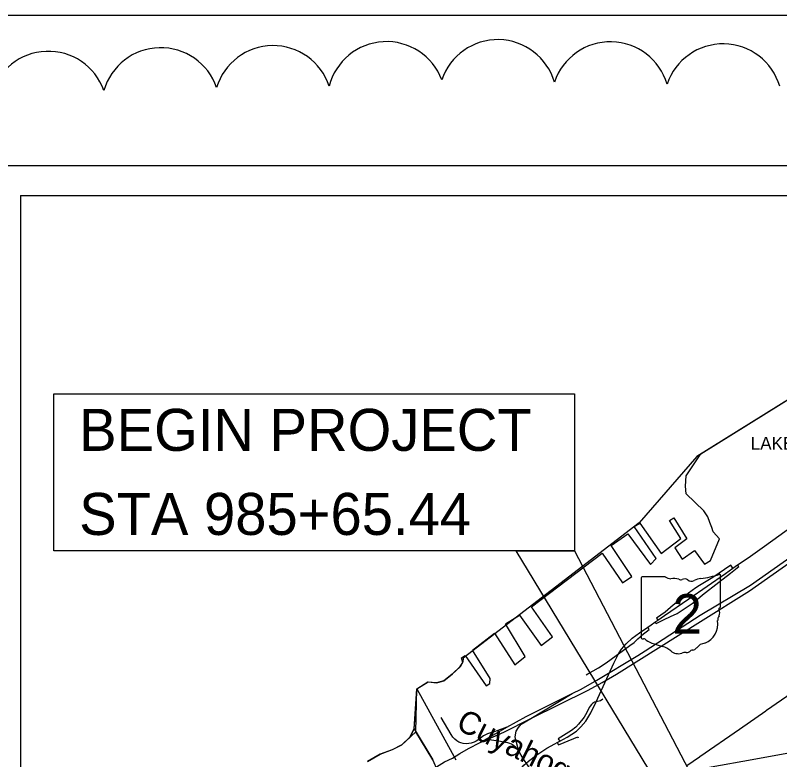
# Model space of a CAD drawing. Extents: x 0 to 96.2, y -27.5 to 31.3.
# Drawn here: x 43.806 to 46.354, y 18.907 to 21.387 of the extents above; entities that cross this region are included whole.
import ezdxf

# ---------------------------------------------------------------- set-up
doc = ezdxf.new("R2010")
doc.units = 0
for name, color, linetype in [('BOTTOM-BLKS', 7, 'Continuous'), ('DIM', 7, 'Continuous'), ('TB1', 7, 'Continuous'), ('TB_DUAL_PROF', 7, 'Continuous'), ('TB_INDEX', 7, 'Continuous'), ('TB_PIPEMAT', 7, 'Continuous'), ('TB_PP_20x10', 7, 'Continuous'), ('TB_PP_30x10_GRID', 7, 'Continuous'), ('TB_PP_50x10_GRID', 7, 'Continuous'), ('TB_PROF_20x5_GRID', 7, 'Continuous'), ('TB_PSDSOD', 7, 'Continuous'), ('TB_SIGN_XS', 7, 'Continuous'), ('TB_SUPER_50x1', 7, 'Continuous'), ('TB_SUPER_50x1_GRID', 7, 'Continuous')]:
    doc.layers.add(name, color=color, linetype=linetype)

msp = doc.modelspace()

# ---------------------------------------------------------------- linework, layer by layer
at = {"layer": 'BOTTOM-BLKS'}
msp.add_lwpolyline([(47.5697, 20.7869), (47.5549, 20.7755), (47.5401, 20.7686), (47.3142, 20.6769), (47.2957, 20.6616), (47.2821, 20.6527), (47.2613, 20.6537), (46.0779, 19.9176), (45.8857, 19.6966), (45.2991, 19.2457), (45.2981, 19.2331), (45.2884, 19.2171), (45.2624, 19.1925), (45.2337, 19.1699), (45.2098, 19.1632), (45.181, 19.166), (45.1439, 19.1425), (45.1344, 19.0097), (45.1214, 18.9823), (45.0939, 18.9569), (45.0625, 18.9403), (45.0216, 18.9255), (44.9794, 18.9013)], dxfattribs=at)
at = {"layer": 'DIM'}
msp.add_lwpolyline([(43.2234, 21.3869), (74.7234, 21.3869), (74.7234, 0.3869), (43.2234, 0.3869)], close=True, dxfattribs=at)
at = {"layer": 'TB1'}
for p, q in [((43.7234, 20.8869), (50.7234, 20.8869)), ((43.8234, 20.7869), (43.8234, 13.9869)), ((43.8234, 20.7869), (50.6234, 20.7869))]:
    msp.add_line(p, q, dxfattribs=at)
at = {"layer": 'TB_DUAL_PROF'}
for p, q in [((45.9722, 19.5167), (45.895, 19.5167)), ((46.156, 19.4169), (46.156, 19.5216)), ((45.8924, 19.5132), (45.8924, 19.3131)), ((46.156, 19.417), (46.156, 19.4169))]:
    msp.add_line(p, q, dxfattribs=at)
for centre, radius, start, end in [((45.8954, 19.5136), 0.00305, 98.1301, 188.1301), ((45.9906, 19.5399), 0.0296, 231.6195, 271.1119), ((46.0621, 19.7895), 0.2796, 275.8445, 288.9065), ((46.1531, 19.5221), 0.00294, 351.8621, 97.738), ((46.0004, 19.4043), 0.1064, 80.4867, 94.9883), ((46.0245, 19.5147), 0.00855, 219.7921, 297.1024), ((46.0371, 19.4916), 0.0178, 54.4667, 119.1411), ((46.06, 19.5233), 0.0214, 233.8562, 294.8282), ((46.0978, 19.4555), 0.0563, 97.3462, 120.7689), ((46.1554, 19.4093), 0.00454, 107.944, 210.337), ((46.1529, 19.4165), 0.00314, 289.6038, 7.7341), ((46.1265, 19.396), 0.0273, 340.033, 23.6496), ((46.0778, 19.3598), 0.0699, 292.3089, 8.9858), ((46.1666, 19.3731), 0.0198, 136.8065, 186.9296), ((45.8954, 19.3127), 0.00308, 171.9584, 258.3066), ((45.8959, 19.3331), 0.0235, 267.339, 280.6039), ((45.9007, 19.3016), 0.00848, 29.7484, 93.2717), ((46.0078, 19.4814), 0.2019, 240.4129, 257.1985), ((46.1073, 19.2569), 0.0383, 94.4031, 142.5768), ((45.9476, 19.2232), 0.0632, 47.1842, 75.836), ((46.0159, 19.3006), 0.0401, 230.7004, 286.2918), ((46.0391, 19.2314), 0.0329, 85.6951, 111.2099), ((46.042, 19.2856), 0.0214, 268.777, 315.5493), ((46.0613, 19.2662), 0.00601, 65.7517, 132.6484), ((46.0587, 19.2937), 0.0226, 282.8732, 323.2771)]:
    msp.add_arc(centre, radius, start, end, dxfattribs=at)
at = {"layer": 'TB_INDEX'}
for points in [[(45.2973, 19.2309), (45.2927, 19.2462), (45.3055, 19.2547), (45.3755, 19.1539), (45.3871, 19.1609), (45.3884, 19.1777), (45.3303, 19.2726), (45.4027, 19.3285), (45.4709, 19.2234), (45.505, 19.2506), (45.4402, 19.3599), (45.4861, 19.3883), (45.5591, 19.2879), (45.5963, 19.317), (45.5259, 19.4163), (45.7621, 19.5956), (45.8302, 19.4962), (45.8302, 19.4962), (45.861, 19.5172), (45.7921, 19.6211), (45.847, 19.6592), (45.9227, 19.5581), (45.9414, 19.577), (45.8682, 19.6843), (45.887, 19.6956), (45.9589, 19.5944), (46.0239, 19.6441), (45.9865, 19.704), (46.0011, 19.7129), (46.044, 19.6432), (46.0039, 19.6133), (46.0284, 19.5753), (46.0701, 19.6037), (46.1035, 19.5589), (46.1227, 19.5706), (46.1535, 19.643), (46.1314, 19.6662), (46.1278, 19.681), (46.1203, 19.6972), (46.1143, 19.7165), (46.1003, 19.7361), (46.042, 19.793), (46.0397, 19.8181), (46.0419, 19.8527), (46.0911, 19.9258)], [(45.1413, 19.0003), (45.1448, 19.143)], [(45.1448, 19.143), (45.2744, 18.9074)], [(45.1448, 19.143), (45.2744, 18.9074)], [(45.1353, 19.0102), (45.1974, 18.9074)], [(45.1974, 18.9074), (45.1413, 19.0003)], [(45.2137, 18.869), (45.1974, 18.9074)]]:
    msp.add_lwpolyline(points, dxfattribs=at)
at = {"layer": 'TB_PIPEMAT'}
msp.add_line((45.1413, 19.0003), (45.1448, 19.143), dxfattribs=at)
for points in [[(46.0911, 19.9258), (47.2621, 20.6542), (47.283, 20.6532), (47.288, 20.6565)], [(45.2973, 19.2309), (45.2927, 19.2462), (45.3055, 19.2547), (45.3755, 19.1539), (45.3871, 19.1609), (45.3884, 19.1777), (45.3303, 19.2726), (45.4027, 19.3285), (45.4709, 19.2234), (45.505, 19.2506), (45.4402, 19.3599), (45.4861, 19.3883), (45.5591, 19.2879), (45.5963, 19.317), (45.5259, 19.4163), (45.7621, 19.5956), (45.8302, 19.4962), (45.8302, 19.4962), (45.861, 19.5172), (45.7921, 19.6211), (45.847, 19.6592), (45.9227, 19.5581), (45.9414, 19.577), (45.8682, 19.6843), (45.887, 19.6956), (45.9589, 19.5944), (46.0239, 19.6441), (45.9865, 19.704), (46.0011, 19.7129), (46.044, 19.6432), (46.0039, 19.6133), (46.0284, 19.5753), (46.0701, 19.6037), (46.1035, 19.5589), (46.1227, 19.5706), (46.1535, 19.643), (46.1314, 19.6662), (46.1278, 19.681), (46.1203, 19.6972), (46.1143, 19.7165), (46.1003, 19.7361), (46.042, 19.793), (46.0397, 19.8181), (46.0419, 19.8527), (46.0911, 19.9258)], [(45.2973, 19.2309), (45.2927, 19.2462), (45.3055, 19.2547), (45.3755, 19.1539), (45.3871, 19.1609), (45.3884, 19.1777), (45.3303, 19.2726), (45.4027, 19.3285), (45.4709, 19.2234), (45.505, 19.2506), (45.4402, 19.3599), (45.4861, 19.3883), (45.5591, 19.2879), (45.5963, 19.317), (45.5259, 19.4163), (45.7621, 19.5956), (45.8302, 19.4962), (45.8302, 19.4962), (45.861, 19.5172), (45.7921, 19.6211), (45.847, 19.6592), (45.9227, 19.5581), (45.9414, 19.577), (45.8682, 19.6843), (45.887, 19.6956), (45.9589, 19.5944), (46.0239, 19.6441), (45.9865, 19.704), (46.0011, 19.7129), (46.044, 19.6432), (46.0039, 19.6133), (46.0284, 19.5753), (46.0701, 19.6037), (46.1035, 19.5589), (46.1227, 19.5706), (46.1535, 19.643), (46.1314, 19.6662), (46.1278, 19.681), (46.1203, 19.6972), (46.1143, 19.7165), (46.1003, 19.7361), (46.042, 19.793), (46.0397, 19.8181), (46.0419, 19.8527), (46.0911, 19.9258)], [(44.9802, 18.9018), (45.0224, 18.926), (45.0633, 18.9408), (45.0947, 18.9574), (45.1222, 18.9827), (45.1353, 19.0102), (45.1448, 19.143), (45.1818, 19.1665), (45.2107, 19.1637), (45.2345, 19.1703), (45.2632, 19.193), (45.2892, 19.2176), (45.2973, 19.2309)], [(45.1448, 19.143), (45.1818, 19.1665), (45.2107, 19.1637), (45.2345, 19.1703), (45.2632, 19.193), (45.2892, 19.2176), (45.2973, 19.2309)], [(44.9802, 18.9018), (45.0224, 18.926), (45.0633, 18.9408), (45.0947, 18.9574), (45.1413, 19.0003)]]:
    msp.add_lwpolyline(points, dxfattribs=at)
at = {"layer": 'TB_PP_50x10_GRID'}
for points in [[(45.9055, 19.2703), (46.0888, 19.3884), (46.2568, 19.4882), (46.6429, 19.7608), (46.9371, 19.9661), (47.0729, 20.0637), (47.1791, 20.1395), (47.2478, 20.1879), (47.3438, 20.2535), (47.478, 20.3432), (47.913, 20.6171), (48.0033, 20.6774)], [(45.5238, 19.0447), (45.7156, 19.1389), (45.7618, 19.165), (45.8095, 19.1926), (46.0898, 19.368), (46.2526, 19.4701), (46.4704, 19.6234), (46.5126, 19.6515), (46.5391, 19.6663), (46.5763, 19.6846), (46.6015, 19.6954), (46.6221, 19.7035), (46.6462, 19.7132), (46.9167, 19.8209), (46.9722, 19.8425)], [(45.6618, 19.1283), (45.6915, 19.1425), (45.7438, 19.1721), (45.8804, 19.2541), (45.9055, 19.2703)], [(45.4443, 19.0158), (45.5081, 19.0509), (45.6618, 19.1283)], [(45.5238, 19.0447), (45.6618, 19.1283)], [(45.4443, 19.0158), (45.4144, 19.0044), (45.4024, 19.0005), (45.39, 18.9969), (45.3797, 18.9933), (45.3734, 18.9907), (45.3669, 18.9871), (45.3568, 18.9789), (45.3478, 18.9723), (45.342, 18.9687), (45.335, 18.9654), (45.3255, 18.9626), (45.3176, 18.9611), (45.3084, 18.9604), (45.2989, 18.9611), (45.2912, 18.9634), (45.284, 18.9662), (45.2777, 18.97), (45.2705, 18.9755), (45.2637, 18.9827), (45.2586, 18.991), (45.2248, 19.0476)], [(45.3553, 18.965), (45.4347, 18.9996), (45.5238, 19.0447)], [(45.4847, 18.9357), (45.4763, 18.9641), (45.4715, 18.9835), (45.4753, 19.0028), (45.4831, 19.0147), (45.4925, 19.0256), (45.5238, 19.0447)], [(45.3553, 18.965), (45.4443, 19.0158)], [(45.2067, 18.8816), (45.219, 18.8888), (45.2368, 18.9004), (45.2627, 18.9129), (45.2872, 18.9277), (45.3161, 18.9449), (45.3553, 18.965)], [(45.4847, 18.9357), (45.4744, 18.9485), (45.4666, 18.9549), (45.4592, 18.9593), (45.454, 18.9615), (45.4472, 18.9637), (45.4402, 18.965), (45.4233, 18.9676), (45.408, 18.9699), (45.3861, 18.9731), (45.3553, 18.965)], [(45.5811, 18.8033), (45.5323, 18.8629), (45.4988, 18.9115), (45.4847, 18.9357)]]:
    msp.add_lwpolyline(points, dxfattribs=at)
at = {"layer": 'TB_PROF_20x5_GRID'}
for points in [[(46.1977, 19.545), (46.1904, 19.5551), (46.1309, 19.5146), (46.0862, 19.4878), (46.0741, 19.48), (46.0495, 19.4623), (46.0421, 19.4572)], [(46.0614, 19.4271), (46.0717, 19.4354), (46.0962, 19.4561), (46.1503, 19.4985), (46.1891, 19.5284), (46.2169, 19.5507), (46.2133, 19.5561)], [(46.0421, 19.4572), (46.0347, 19.4513), (45.9983, 19.4217), (45.9716, 19.399), (45.9429, 19.3785), (45.9474, 19.3721)], [(45.938, 19.3656), (45.9414, 19.3609), (45.968, 19.3746), (45.9894, 19.3845), (46.0117, 19.3948), (46.0523, 19.4207), (46.0614, 19.4271)], [(45.709, 19.1901), (45.7146, 19.1934), (45.7492, 19.2137), (45.7753, 19.2305), (45.8085, 19.254), (45.8163, 19.2597), (45.8544, 19.2875), (45.8682, 19.2981), (45.8804, 19.3097), (45.8882, 19.3168), (45.8943, 19.322), (45.9185, 19.3412), (45.9139, 19.3485)], [(45.7638, 19.1094), (45.7561, 19.1034), (45.7414, 19.1004), (45.7369, 19.0989), (45.7334, 19.0971), (45.7298, 19.0946), (45.7264, 19.0915), (45.7221, 19.086), (45.719, 19.0809), (45.7108, 19.065), (45.7015, 19.0487), (45.6836, 19.0257), (45.6739, 19.0162), (45.6595, 19.0047), (45.6154, 18.9765), (45.6203, 18.9688)], [(45.6118, 18.9641), (45.6159, 18.9573), (45.6357, 18.9646), (45.6804, 18.9832), (45.682, 18.9807)]]:
    msp.add_lwpolyline(points, dxfattribs=at)
at = {"layer": 'TB_PSDSOD'}
for points in [[(46.3027, 19.6188), (46.4181, 19.7014), (46.4434, 19.7217), (46.4749, 19.7497), (46.5398, 19.8203), (46.5853, 19.8679), (46.6096, 19.8906), (46.6375, 19.9139), (46.6726, 19.9395), (46.6779, 19.9434)], [(46.1735, 19.5276), (46.1977, 19.545), (46.2133, 19.5561), (46.248, 19.5796), (46.3027, 19.6188)], [(46.0508, 19.4431), (46.173, 19.5272), (46.1735, 19.5276)], [(45.9702, 19.3878), (46.0508, 19.4431)], [(45.9139, 19.3485), (45.9247, 19.3563), (45.938, 19.3656), (45.9474, 19.3721), (45.9702, 19.3878)], [(45.6203, 18.9688), (45.6454, 18.982), (45.6768, 19.0022), (45.6912, 19.0172), (45.7072, 19.036), (45.7246, 19.0636), (45.7414, 19.1004), (45.7535, 19.1245), (45.8013, 19.2287), (45.8163, 19.2597), (45.8264, 19.275), (45.8414, 19.2929), (45.8617, 19.3122), (45.8858, 19.3301), (45.9139, 19.3485)], [(45.335, 18.5851), (45.3527, 18.6378), (45.3746, 18.6819), (45.4782, 18.8571), (45.4899, 18.8748), (45.5005, 18.8888), (45.5159, 18.9023), (45.544, 18.924), (45.5776, 18.9457), (45.604, 18.9599), (45.6118, 18.9641), (45.6203, 18.9688)]]:
    msp.add_lwpolyline(points, dxfattribs=at)
at = {"layer": 'TB_SIGN_XS'}
for points in [[(46.3093, 19.0718), (46.4274, 19.1536), (46.4334, 19.1578)], [(46.086, 18.9171), (46.0873, 18.918), (46.2194, 19.0095), (46.3069, 19.0702), (46.3093, 19.0718)], [(46.1129, 18.881), (46.1135, 18.8815), (46.2738, 18.9107), (46.4021, 18.9331)], [(46.0446, 18.8884), (46.086, 18.9171)]]:
    msp.add_lwpolyline(points, dxfattribs=at)
at = {"layer": 'TB_SUPER_50x1'}
for points in [[(43.9343, 20.1257), (45.6693, 20.1257), (45.6693, 19.6035), (43.9343, 19.6035)], [(45.6693, 19.6035), (46.8555, 17.3299), (45.4754, 19.6035)]]:
    msp.add_lwpolyline(points, close=True, dxfattribs=at)
at = {"layer": 'TB_SUPER_50x1_GRID'}
for centre, radius, start, end in [((45.0431, 21.1021), 0.1971, 20.6866, 165.6866), ((45.4141, 21.109), 0.1968, 16.4231, 161.4231), ((45.7895, 21.1019), 0.1968, 16.4231, 161.4231), ((44.2905, 21.0821), 0.1969, 18.9488, 163.9488), ((44.6652, 21.0892), 0.1968, 18.2245, 163.2245), ((46.1648, 21.0949), 0.1968, 16.4231, 161.4231), ((43.916, 21.0701), 0.1969, 19.7178, 164.7178)]:
    msp.add_arc(centre, radius, start, end, dxfattribs=at)

# ---------------------------------------------------------------- texts
at = {"layer": 'TB_DUAL_PROF'}
msp.add_text('2', height=0.1318, dxfattribs=at).set_placement((45.9962, 19.3272))
at = {"layer": 'TB_PP_20x10'}
msp.add_text('Cuyahoga', height=0.0758, rotation=333.5835, dxfattribs=at).set_placement((45.2709, 19.0115))
at = {"layer": 'TB_PP_30x10_GRID'}
msp.add_text('LAKEFRONT', height=0.04261, rotation=0, dxfattribs=at).set_placement((46.2569, 19.9399))
at = {"layer": 'TB_SUPER_50x1'}
for s, p in [('BEGIN PROJECT', (44.0188, 19.936)), ('STA 985+65.44', (44.0188, 19.656))]:
    msp.add_text(s, height=0.14, dxfattribs=at).set_placement(p)

doc.saveas('drawing.dxf')
